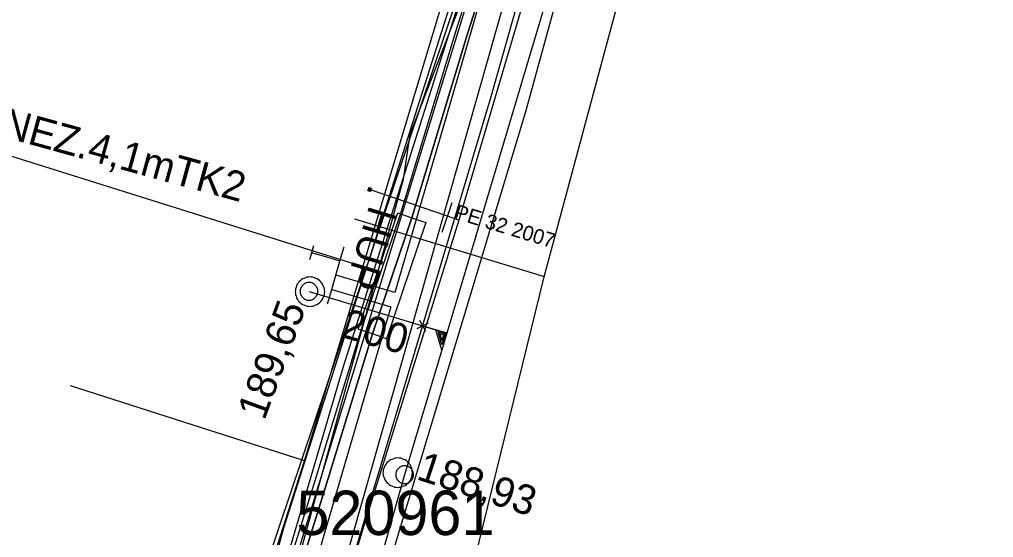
# Model space of a CAD drawing. Extents: x -746464 to -745690, y -1051581 to -1049993.
# Drawn here: x -746104.52 to -746071.61, y -1050654.06 to -1050636.55 of the extents above; entities that cross this region are included whole.
import ezdxf

# ---------------------------------------------------------------- set-up
doc = ezdxf.new("R2010")
doc.units = 0
for name, color, linetype in [('04_CETIN_neprovozovane', 7, 'Continuous'), ('04_CETIN_sdelovaci_podzem', 7, 'Continuous'), ('37_TVNET_sdelovaci_televizni kabely', 7, 'Continuous'), ('45_Eltodo_napajeci_kabel_NN', 7, 'Continuous'), ('45_Eltodo_popisy', 7, 'Continuous'), ('45_Eltodo_vedeni_NN_zemni', 7, 'Continuous'), ('48_Prazs_plynarenska_STL', 7, 'Continuous'), ('48_Prazs_plynarenska_STL_popisy', 7, 'Continuous'), ('51_PVaK_kanal_jednotna_neoverena poloha_pripojka', 7, 'Continuous'), ('51_PVaK_kanal_jednotna_overena poloha_rad', 7, 'Continuous'), ('51_PVaK_kanal_objekty', 7, 'Continuous'), ('51_PVaK_kanal_popisy', 7, 'Continuous'), ('51_PVaK_vodovod_chranicky_objekty', 7, 'Continuous'), ('51_PVaK_vodovod_NEPROVOZUJE PVK_neoverene poloha', 7, 'Continuous'), ('55_PREdi_chranicky', 7, 'Continuous'), ('55_PREdi_NN', 7, 'Continuous'), ('55_PREdi_NN_pripojovaci_misto', 7, 'Continuous'), ('55_PREdi_stavby_popisy', 7, 'Continuous'), ('55_PREdi_VN', 7, 'Continuous'), ('55_PREdi_ZRUSENE_elektro', 7, 'Continuous')]:
    doc.layers.add(name, color=color, linetype=linetype)

msp = doc.modelspace()

# ---------------------------------------------------------------- linework, layer by layer
at = {"layer": '04_CETIN_neprovozovane'}
msp.add_lwpolyline([(-746122.86, -1050802.08), (-746120.21, -1050779.57), (-746117.76, -1050758.96), (-746115.41, -1050737.5), (-746111.78, -1050719.1), (-746081.26, -1050611.75), (-746077.75, -1050600.04)], dxfattribs=at)
at = {"layer": '04_CETIN_sdelovaci_podzem'}
msp.add_lwpolyline([(-746096.68, -1050660.58), (-746091.55, -1050641.95), (-746091.32, -1050640.43), (-746089.12, -1050634.74), (-746088.43, -1050633.62)], dxfattribs=at)
at = {"layer": '37_TVNET_sdelovaci_televizni kabely'}
for points in [[(-745984.595, -1050626.363), (-746079.15, -1050602.616), (-746117.902, -1050728.62), (-746140.499, -1050964.785), (-746150.343, -1051014.385), (-746134.374, -1051025.766), (-746053.56, -1051028.358)], [(-746094.89, -1050651.467), (-746085.452, -1050620.079), (-746092.235, -1050618.04)], [(-746118.296, -1050724.621), (-746094.89, -1050651.467), (-746102.801, -1050648.936)]]:
    msp.add_lwpolyline(points, dxfattribs=at)
at = {"layer": '45_Eltodo_napajeci_kabel_NN'}
msp.add_lwpolyline([(-746120.222, -1050780.456), (-746117.893, -1050761.331), (-746115.771, -1050739.469), (-746111.954, -1050718.14), (-746112.159, -1050718.76), (-746102.169, -1050679.37), (-746100.421, -1050672.083), (-746096.865, -1050659.485), (-746093.587, -1050648.313), (-746077.373, -1050597.206), (-746063.594, -1050600.606), (-746044.898, -1050606.017), (-746045.886, -1050609.461)], dxfattribs=at)
at = {"layer": '45_Eltodo_vedeni_NN_zemni'}
for points in [[(-746095.596, -1050653.737), (-746089.311, -1050634)], [(-746101.489, -1050675.417), (-746095.596, -1050653.737)]]:
    msp.add_lwpolyline(points, dxfattribs=at)
at = {"layer": '48_Prazs_plynarenska_STL'}
for points in [[(-746115.164, -1050775.276), (-746114.581, -1050769.606), (-746114.401, -1050767.848), (-746113.67, -1050760.737), (-746113.57, -1050759.76), (-746112.697, -1050753.167), (-746110.88, -1050739.44), (-746109.5, -1050728.87), (-746105.616, -1050714.089), (-746102.18, -1050701.01), (-746092.81, -1050669.78), (-746086.791, -1050645.246), (-746082.87, -1050630.67), (-746075.19, -1050609.92), (-746073.343, -1050606.911), (-746072.119, -1050604.92)], [(-746087.078, -1050645.159), (-746093.194, -1050643.3)], [(-746086.791, -1050645.246), (-746087.078, -1050645.159)]]:
    msp.add_lwpolyline(points, dxfattribs=at)
at = {"layer": '51_PVaK_kanal_jednotna_neoverena poloha_pripojka'}
msp.add_line((-746094.74, -1050645.74), (-746090.081, -1050647.148), dxfattribs=at)
at = {"layer": '51_PVaK_kanal_jednotna_overena poloha_rad'}
for points in [[(-746078.89, -1050609.61), (-746090.081, -1050647.148), (-746091.51, -1050651.94)], [(-746091.51, -1050651.94), (-746095.349, -1050665.451), (-746104.26, -1050696.81)]]:
    msp.add_lwpolyline(points, dxfattribs=at)
at = {"layer": '51_PVaK_kanal_objekty'}
for p, q in [((-746091.08, -1050647.001), (-746090.707, -1050646.799)), ((-746090.791, -1050647.095), (-746090.992, -1050646.726))]:
    msp.add_line(p, q, dxfattribs=at)
for points in [[(-746094.21, -1050645.75), (-746094.22, -1050645.7), (-746094.22, -1050645.65), (-746094.24, -1050645.6), (-746094.26, -1050645.55), (-746094.28, -1050645.5), (-746094.31, -1050645.46), (-746094.34, -1050645.42), (-746094.38, -1050645.38), (-746094.42, -1050645.35), (-746094.46, -1050645.32), (-746094.51, -1050645.3), (-746094.56, -1050645.28), (-746094.61, -1050645.26), (-746094.66, -1050645.26), (-746094.71, -1050645.25), (-746094.76, -1050645.26), (-746094.81, -1050645.26), (-746094.86, -1050645.28), (-746094.91, -1050645.3), (-746094.96, -1050645.32), (-746095, -1050645.35), (-746095.04, -1050645.38), (-746095.08, -1050645.42), (-746095.11, -1050645.46), (-746095.14, -1050645.5), (-746095.16, -1050645.55), (-746095.18, -1050645.6), (-746095.2, -1050645.65), (-746095.2, -1050645.7), (-746095.21, -1050645.75), (-746095.2, -1050645.8), (-746095.2, -1050645.85), (-746095.18, -1050645.9), (-746095.16, -1050645.95), (-746095.14, -1050646), (-746095.11, -1050646.04), (-746095.08, -1050646.08), (-746095.04, -1050646.12), (-746095, -1050646.15), (-746094.96, -1050646.18), (-746094.91, -1050646.2), (-746094.86, -1050646.22), (-746094.81, -1050646.24), (-746094.76, -1050646.24), (-746094.71, -1050646.25), (-746094.66, -1050646.24), (-746094.61, -1050646.24), (-746094.56, -1050646.22), (-746094.51, -1050646.2), (-746094.46, -1050646.18), (-746094.42, -1050646.15), (-746094.38, -1050646.12), (-746094.34, -1050646.08), (-746094.31, -1050646.04), (-746094.28, -1050646), (-746094.26, -1050645.95), (-746094.24, -1050645.9), (-746094.22, -1050645.85), (-746094.22, -1050645.8), (-746094.21, -1050645.75)], [(-746094.44, -1050645.74), (-746094.44, -1050645.71), (-746094.446, -1050645.68), (-746094.452, -1050645.65), (-746094.464, -1050645.62), (-746094.482, -1050645.59), (-746094.5, -1050645.566), (-746094.518, -1050645.542), (-746094.542, -1050645.518), (-746094.566, -1050645.5), (-746094.59, -1050645.482), (-746094.62, -1050645.464), (-746094.65, -1050645.452), (-746094.68, -1050645.446), (-746094.71, -1050645.44), (-746094.74, -1050645.44), (-746094.77, -1050645.44), (-746094.8, -1050645.446), (-746094.83, -1050645.452), (-746094.86, -1050645.464), (-746094.89, -1050645.482), (-746094.914, -1050645.5), (-746094.938, -1050645.518), (-746094.962, -1050645.542), (-746094.98, -1050645.566), (-746094.998, -1050645.59), (-746095.016, -1050645.62), (-746095.028, -1050645.65), (-746095.034, -1050645.68), (-746095.04, -1050645.71), (-746095.04, -1050645.74), (-746095.04, -1050645.77), (-746095.034, -1050645.8), (-746095.028, -1050645.83), (-746095.016, -1050645.86), (-746094.998, -1050645.89), (-746094.98, -1050645.914), (-746094.962, -1050645.938), (-746094.938, -1050645.962), (-746094.914, -1050645.98), (-746094.89, -1050645.998), (-746094.86, -1050646.016), (-746094.83, -1050646.028), (-746094.8, -1050646.034), (-746094.77, -1050646.04), (-746094.74, -1050646.04), (-746094.71, -1050646.04), (-746094.68, -1050646.034), (-746094.65, -1050646.028), (-746094.62, -1050646.016), (-746094.59, -1050645.998), (-746094.566, -1050645.98), (-746094.542, -1050645.962), (-746094.518, -1050645.938), (-746094.5, -1050645.914), (-746094.482, -1050645.89), (-746094.464, -1050645.86), (-746094.452, -1050645.83), (-746094.446, -1050645.8), (-746094.44, -1050645.77), (-746094.44, -1050645.74)], [(-746090.896, -1050646.903), (-746090.082, -1050647.146), (-746090.256, -1050647.726), (-746090.45, -1050647.036)], [(-746090.381, -1050647.103), (-746090.144, -1050647.174), (-746090.254, -1050647.545), (-746090.38, -1050647.099)], [(-746090.308, -1050647.171), (-746090.19, -1050647.207), (-746090.246, -1050647.397), (-746090.307, -1050647.168)], [(-746091.24, -1050651.87), (-746091.25, -1050651.82), (-746091.25, -1050651.77), (-746091.27, -1050651.72), (-746091.29, -1050651.67), (-746091.31, -1050651.62), (-746091.34, -1050651.58), (-746091.37, -1050651.54), (-746091.41, -1050651.5), (-746091.45, -1050651.47), (-746091.49, -1050651.44), (-746091.54, -1050651.42), (-746091.59, -1050651.4), (-746091.64, -1050651.38), (-746091.69, -1050651.38), (-746091.74, -1050651.37), (-746091.79, -1050651.38), (-746091.84, -1050651.38), (-746091.89, -1050651.4), (-746091.94, -1050651.42), (-746091.99, -1050651.44), (-746092.03, -1050651.47), (-746092.07, -1050651.5), (-746092.11, -1050651.54), (-746092.14, -1050651.58), (-746092.17, -1050651.62), (-746092.19, -1050651.67), (-746092.21, -1050651.72), (-746092.23, -1050651.77), (-746092.23, -1050651.82), (-746092.24, -1050651.87), (-746092.23, -1050651.92), (-746092.23, -1050651.97), (-746092.21, -1050652.02), (-746092.19, -1050652.07), (-746092.17, -1050652.12), (-746092.14, -1050652.16), (-746092.11, -1050652.2), (-746092.07, -1050652.24), (-746092.03, -1050652.27), (-746091.99, -1050652.3), (-746091.94, -1050652.32), (-746091.89, -1050652.34), (-746091.84, -1050652.36), (-746091.79, -1050652.36), (-746091.74, -1050652.37), (-746091.69, -1050652.36), (-746091.64, -1050652.36), (-746091.59, -1050652.34), (-746091.54, -1050652.32), (-746091.49, -1050652.3), (-746091.45, -1050652.27), (-746091.41, -1050652.24), (-746091.37, -1050652.2), (-746091.34, -1050652.16), (-746091.31, -1050652.12), (-746091.29, -1050652.07), (-746091.27, -1050652.02), (-746091.25, -1050651.97), (-746091.25, -1050651.92), (-746091.24, -1050651.87)], [(-746091.21, -1050651.94), (-746091.21, -1050651.91), (-746091.216, -1050651.88), (-746091.222, -1050651.85), (-746091.234, -1050651.82), (-746091.252, -1050651.79), (-746091.27, -1050651.766), (-746091.288, -1050651.742), (-746091.312, -1050651.718), (-746091.336, -1050651.7), (-746091.36, -1050651.682), (-746091.39, -1050651.664), (-746091.42, -1050651.652), (-746091.45, -1050651.646), (-746091.48, -1050651.64), (-746091.51, -1050651.64), (-746091.54, -1050651.64), (-746091.57, -1050651.646), (-746091.6, -1050651.652), (-746091.63, -1050651.664), (-746091.66, -1050651.682), (-746091.684, -1050651.7), (-746091.708, -1050651.718), (-746091.732, -1050651.742), (-746091.75, -1050651.766), (-746091.768, -1050651.79), (-746091.786, -1050651.82), (-746091.798, -1050651.85), (-746091.804, -1050651.88), (-746091.81, -1050651.91), (-746091.81, -1050651.94), (-746091.81, -1050651.97), (-746091.804, -1050652), (-746091.798, -1050652.03), (-746091.786, -1050652.06), (-746091.768, -1050652.09), (-746091.75, -1050652.114), (-746091.732, -1050652.138), (-746091.708, -1050652.162), (-746091.684, -1050652.18), (-746091.66, -1050652.198), (-746091.63, -1050652.216), (-746091.6, -1050652.228), (-746091.57, -1050652.234), (-746091.54, -1050652.24), (-746091.51, -1050652.24), (-746091.48, -1050652.24), (-746091.45, -1050652.234), (-746091.42, -1050652.228), (-746091.39, -1050652.216), (-746091.36, -1050652.198), (-746091.336, -1050652.18), (-746091.312, -1050652.162), (-746091.288, -1050652.138), (-746091.27, -1050652.114), (-746091.252, -1050652.09), (-746091.234, -1050652.06), (-746091.222, -1050652.03), (-746091.216, -1050652), (-746091.21, -1050651.97), (-746091.21, -1050651.94)]]:
    msp.add_lwpolyline(points, dxfattribs=at)
at = {"layer": '51_PVaK_vodovod_chranicky_objekty'}
for p, q in [((-746092.722, -1050642.233), (-746092.728, -1050642.252)), ((-746092.722, -1050642.233), (-746092.659, -1050642.36)), ((-746092.722, -1050642.233), (-746092.703, -1050642.24)), ((-746092.754, -1050642.328), (-746092.627, -1050642.266)), ((-746092.754, -1050642.328), (-746092.748, -1050642.309)), ((-746092.754, -1050642.328), (-746092.735, -1050642.334)), ((-746092.659, -1050642.36), (-746092.678, -1050642.354)), ((-746092.659, -1050642.36), (-746092.653, -1050642.341)), ((-746092.627, -1050642.266), (-746092.646, -1050642.259)), ((-746092.627, -1050642.266), (-746092.634, -1050642.285)), ((-746090.243, -1050643.74), (-746089.904, -1050642.74))]:
    msp.add_line(p, q, dxfattribs=at)
msp.add_lwpolyline([(-746092.643, -1050642.313), (-746092.642, -1050642.308), (-746092.641, -1050642.303), (-746092.64, -1050642.298), (-746092.641, -1050642.293), (-746092.642, -1050642.287), (-746092.643, -1050642.282), (-746092.645, -1050642.277), (-746092.647, -1050642.272), (-746092.65, -1050642.268), (-746092.653, -1050642.264), (-746092.657, -1050642.26), (-746092.661, -1050642.256), (-746092.665, -1050642.254), (-746092.67, -1050642.251), (-746092.674, -1050642.249), (-746092.679, -1050642.248), (-746092.684, -1050642.247), (-746092.689, -1050642.246), (-746092.695, -1050642.247), (-746092.7, -1050642.248), (-746092.705, -1050642.249), (-746092.71, -1050642.251), (-746092.715, -1050642.253), (-746092.719, -1050642.256), (-746092.723, -1050642.259), (-746092.728, -1050642.263), (-746092.731, -1050642.267), (-746092.734, -1050642.271), (-746092.736, -1050642.276), (-746092.738, -1050642.28), (-746092.739, -1050642.285), (-746092.74, -1050642.29), (-746092.741, -1050642.295), (-746092.741, -1050642.301), (-746092.739, -1050642.306), (-746092.738, -1050642.311), (-746092.736, -1050642.316), (-746092.734, -1050642.321), (-746092.731, -1050642.325), (-746092.728, -1050642.329), (-746092.724, -1050642.334), (-746092.72, -1050642.337), (-746092.716, -1050642.34), (-746092.711, -1050642.342), (-746092.707, -1050642.344), (-746092.702, -1050642.346), (-746092.697, -1050642.346), (-746092.692, -1050642.347), (-746092.687, -1050642.347), (-746092.681, -1050642.345), (-746092.676, -1050642.344), (-746092.671, -1050642.342), (-746092.666, -1050642.34), (-746092.662, -1050642.337), (-746092.658, -1050642.334), (-746092.654, -1050642.331), (-746092.65, -1050642.326), (-746092.647, -1050642.322), (-746092.645, -1050642.318), (-746092.643, -1050642.313)], dxfattribs=at)
at = {"layer": '51_PVaK_vodovod_NEPROVOZUJE PVK_neoverene poloha'}
for p, q in [((-746090.06, -1050643.2), (-746092.692, -1050642.297)), ((-746089.682, -1050643.328), (-746090.06, -1050643.2))]:
    msp.add_line(p, q, dxfattribs=at)
msp.add_lwpolyline([(-746081.419, -1050615.368), (-746089.682, -1050643.328), (-746097.066, -1050667.122), (-746097.128, -1050667.322), (-746108.564, -1050709.28), (-746112.17, -1050723.67)], dxfattribs=at)
at = {"layer": '55_PREdi_chranicky'}
msp.add_lwpolyline([(-746091.27, -1050643.25), (-746090.796, -1050643.41), (-746092.126, -1050647.34), (-746092.6, -1050647.18), (-746093.074, -1050647.02), (-746091.744, -1050643.09), (-746091.27, -1050643.25)], close=True, dxfattribs=at)
at = {"layer": '55_PREdi_NN'}
for points in [[(-746079.707, -1050608.094), (-746081.337, -1050613.521), (-746088.598, -1050639.168), (-746100.883, -1050680.307), (-746109.804, -1050710.935), (-746113.542, -1050724.97), (-746114.797, -1050736.143), (-746116.957, -1050755.942), (-746121.273, -1050791.507), (-746121.329, -1050792.488), (-746122.44, -1050801.822), (-746124.772, -1050826.479), (-746132.514, -1050898.319), (-746135.263, -1050933.408), (-746137.115, -1050954.341), (-746141.612, -1050953.806)], [(-746078.666, -1050608.367), (-746080.547, -1050614.642), (-746087.42, -1050639.673), (-746099.733, -1050680.532), (-746108.682, -1050711.888), (-746112.327, -1050725.235), (-746113.87, -1050737.785), (-746116.087, -1050756.251), (-746119.869, -1050789.369)], [(-746088.779, -1050608.772), (-746089.356, -1050610.692), (-746089.447, -1050611.687), (-746082.596, -1050613.928), (-746089.776, -1050638.719), (-746091.84, -1050645.78), (-746093.834, -1050645.197)], [(-746082.618, -1050613.431), (-746085.355, -1050622.762), (-746096.575, -1050656.136), (-746097.2, -1050657.202)], [(-746094.115, -1050646.157), (-746093.974, -1050645.677), (-746093.834, -1050645.197), (-746093.694, -1050644.717), (-746093.553, -1050644.237)], [(-746093.694, -1050644.717), (-746094.173, -1050644.577)], [(-746093.974, -1050645.677), (-746091.98, -1050646.26), (-746095.486, -1050658.248)]]:
    msp.add_lwpolyline(points, dxfattribs=at)
at = {"layer": '55_PREdi_NN_pripojovaci_misto'}
for p, q in [((-746094.585, -1050644.199), (-746094.723, -1050644.679)), ((-746094.173, -1050644.577), (-746094.654, -1050644.439))]:
    msp.add_line(p, q, dxfattribs=at)
at = {"layer": '55_PREdi_stavby_popisy'}
msp.add_lwpolyline([(-746107.195, -1050640.458), (-746106.231, -1050640.723), (-746092.409, -1050645.055)], dxfattribs=at)
at = {"layer": '55_PREdi_VN'}
for points in [[(-746084.26, -1050618.97), (-746084.38, -1050620.68), (-746084.55, -1050621.81), (-746085.44, -1050624.43), (-746086.04, -1050626.17), (-746087.61, -1050632.32), (-746088.87, -1050635.41), (-746089.4, -1050637.07), (-746091.27, -1050643.25), (-746092.6, -1050647.18), (-746094.15, -1050652.25), (-746096.46, -1050659.67), (-746099.15, -1050668.69), (-746101.35, -1050675.37), (-746102.87, -1050681.19)], [(-746102.87, -1050681.19), (-746101.35, -1050675.37), (-746099.15, -1050668.69), (-746096.46, -1050659.67), (-746094.15, -1050652.25), (-746092.6, -1050647.18), (-746091.27, -1050643.25), (-746089.4, -1050637.07), (-746088.87, -1050635.41), (-746087.61, -1050632.32), (-746086.04, -1050626.17), (-746085.44, -1050624.43), (-746084.55, -1050621.81), (-746084.38, -1050620.68)]]:
    msp.add_lwpolyline(points, dxfattribs=at)
at = {"layer": '55_PREdi_ZRUSENE_elektro'}
msp.add_lwpolyline([(-746103.257, -1050681.088), (-746101.734, -1050675.257), (-746099.532, -1050668.57), (-746096.843, -1050659.553), (-746094.532, -1050652.132), (-746092.981, -1050647.057), (-746091.651, -1050643.128), (-746089.782, -1050636.951), (-746089.246, -1050635.273), (-746087.991, -1050632.194), (-746086.424, -1050626.055), (-746085.818, -1050624.3), (-746084.94, -1050621.715)], dxfattribs=at)

# ---------------------------------------------------------------- texts
at = {"layer": '45_Eltodo_popisy'}
msp.add_text('520961', height=1.5, dxfattribs=at).set_placement((-746095.167, -1050653.978))
at = {"layer": '48_Prazs_plynarenska_STL_popisy'}
for s, height, rotation, p in [('PE 32 2007', 0.5, 343.093, (-746089.861, -1050643.268)), ('HUP', 1, 253.09, (-746092.694, -1050642.8))]:
    msp.add_text(s, height=height, rotation=rotation, dxfattribs=at).set_placement(p)
at = {"layer": '51_PVaK_kanal_popisy'}
for s, rotation, p in [('189,65', 69.7958, (-746096.248, -1050650.13)), ('200', 344.1865, (-746093.708, -1050647.27)), ('188,93', 341.8543, (-746091.148, -1050652.081))]:
    msp.add_text(s, height=1, rotation=rotation, dxfattribs=at).set_placement(p)
at = {"layer": '55_PREdi_stavby_popisy'}
msp.add_text('1xNEZ.4,1mTK2', height=1, rotation=344.6296, dxfattribs=at).set_placement((-746106.58, -1050640.109))

doc.saveas('drawing.dxf')
